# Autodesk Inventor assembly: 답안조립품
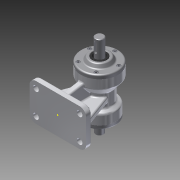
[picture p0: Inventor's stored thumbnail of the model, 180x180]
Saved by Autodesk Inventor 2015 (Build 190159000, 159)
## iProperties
Created: 2015-08
Part Number: 답안조립품
Document SubType Name: Assembly
Designer: PHO-02
Author: PHO-02
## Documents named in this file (10)
- C:\Users\PHO-02\Desktop\450805V1030\답안조립품.iam
- C:\Users\PHO-02\Desktop\450805V1030\본체.ipt
- C:\Users\PHO-02\Desktop\450805V1030\앞커버.ipt
- C:\Users\PHO-02\Desktop\450805V1030\뒤커버.ipt
- C:\Users\PHO-02\Desktop\450805V1030\오일실 .ipt
- 오일실 .ipt
- C:\Users\PHO-02\Desktop\450805V1030\베어링 6203.ipt
- C:\Users\PHO-02\Desktop\450805V1030\베어링 6205.ipt
- C:\Users\PHO-02\Desktop\450805V1030\축.ipt
- C:\Users\PHO-02\Desktop\450805V1030\M4x0.5.ipt
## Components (10 placed, 1 different names)
1. M4x0.5:1 — 각도:1
2. M4x0.5:3
3. M4x0.5:4
4. M4x0.5:5
5. M4x0.5:6
6. M4x0.5:2 — 각도:2
7. M4x0.5:7
8. M4x0.5:8
9. M4x0.5:9
10. M4x0.5:10
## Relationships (2: Angle 2)
- 각도:1 [Angle]: M4x0.5:1
- 각도:2 [Angle]: M4x0.5:2
